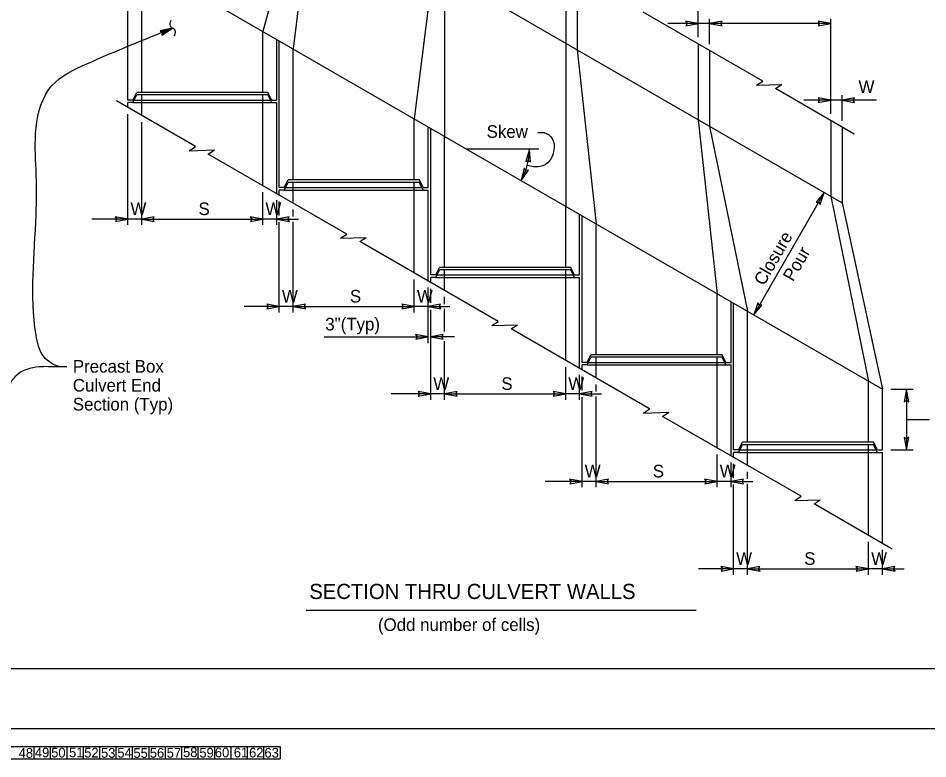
# Model space of a CAD drawing. Extents: x 0 to 2.83, y -0.03 to 1.83.
# Drawn here: x 0.902 to 1.84, y -0.031 to 0.733 of the extents above; entities that cross this region are included whole.
import ezdxf

# ---------------------------------------------------------------- set-up
doc = ezdxf.new("R2010")
doc.units = 0
for name, color, linetype in [('48', 7, 'Continuous'), ('49', 7, 'Continuous'), ('50', 7, 'Continuous'), ('51', 7, 'Continuous'), ('52', 7, 'Continuous'), ('53', 7, 'Continuous'), ('54', 7, 'Continuous'), ('55', 7, 'Continuous'), ('56', 7, 'Continuous'), ('57', 7, 'Continuous'), ('58', 7, 'Continuous'), ('59', 7, 'Continuous'), ('60', 7, 'Continuous'), ('61', 7, 'Continuous'), ('62', 7, 'Continuous'), ('63', 7, 'Continuous'), ('Default', 7, 'Continuous')]:
    doc.layers.add(name, color=color, linetype=linetype)

msp = doc.modelspace()

# ---------------------------------------------------------------- linework, layer by layer
at = {"layer": '50'}
for p, q in [((1.05641, 0.94429), (1.75172, 0.54286)), ((1.01474, 0.80001), (1.79339, 0.35046)), ((1.01995, 0.64881), (1.01474, 0.64881)), ((1.01995, 0.64881), (1.02386, 0.65662)), ((1.01995, 0.6462), (1.02386, 0.65402)), ((1.02125, 0.64881), (1.16188, 0.64881)), ((1.15927, 0.65662), (1.02386, 0.65662)), ((1.15927, 0.65402), (1.02386, 0.65402)), ((1.02906, 0.63277), (1.02906, 0.65402)), ((1.16318, 0.64881), (1.15927, 0.65662)), ((1.16318, 0.6462), (1.15927, 0.65402)), ((1.16318, 0.64881), (1.16839, 0.64881)), ((1.01474, 0.64104), (1.01474, 0.6462)), ((1.01995, 0.6462), (1.01474, 0.6462)), ((1.01995, 0.6462), (1.16318, 0.6462)), ((1.16318, 0.6462), (1.16839, 0.6462)), ((1.1762, 0.5586), (1.18011, 0.56641)), ((1.1762, 0.55599), (1.18011, 0.5638)), ((1.31552, 0.56641), (1.18011, 0.56641)), ((1.31552, 0.5638), (1.18011, 0.5638)), ((1.18531, 0.54256), (1.18531, 0.5638)), ((1.31943, 0.5586), (1.31552, 0.56641)), ((1.31943, 0.55599), (1.31552, 0.5638)), ((1.1762, 0.5586), (1.17099, 0.5586)), ((1.17099, 0.55083), (1.17099, 0.55599)), ((1.1762, 0.55599), (1.17099, 0.55599)), ((1.1762, 0.55599), (1.31943, 0.55599)), ((1.1775, 0.5586), (1.31813, 0.5586)), ((1.31943, 0.5586), (1.32464, 0.5586)), ((1.31943, 0.55599), (1.32464, 0.55599)), ((1.33245, 0.46839), (1.33636, 0.4762)), ((1.33245, 0.46578), (1.33636, 0.47359)), ((1.47177, 0.4762), (1.33636, 0.4762)), ((1.47177, 0.47359), (1.33636, 0.47359)), ((1.34156, 0.45235), (1.34156, 0.47359)), ((1.47568, 0.46839), (1.47177, 0.4762)), ((1.47568, 0.46578), (1.47177, 0.47359)), ((1.33245, 0.46839), (1.32724, 0.46839)), ((1.32724, 0.46062), (1.32724, 0.46578)), ((1.33245, 0.46578), (1.32724, 0.46578)), ((1.33245, 0.46578), (1.47568, 0.46578)), ((1.33375, 0.46839), (1.47438, 0.46839)), ((1.47568, 0.46839), (1.48089, 0.46839)), ((1.47568, 0.46578), (1.48089, 0.46578)), ((1.4887, 0.37817), (1.49261, 0.38599)), ((1.62802, 0.38599), (1.49261, 0.38599)), ((1.63193, 0.37817), (1.62802, 0.38599)), ((1.4887, 0.37817), (1.48349, 0.37817)), ((1.48349, 0.37041), (1.48349, 0.37557)), ((1.4887, 0.37557), (1.48349, 0.37557)), ((1.4887, 0.37557), (1.49261, 0.38338)), ((1.4887, 0.37557), (1.63193, 0.37557)), ((1.49, 0.37817), (1.63063, 0.37817)), ((1.62802, 0.38338), (1.49261, 0.38338)), ((1.49781, 0.36214), (1.49781, 0.38338)), ((1.63193, 0.37557), (1.62802, 0.38338)), ((1.63193, 0.37817), (1.63714, 0.37817)), ((1.63193, 0.37557), (1.63714, 0.37557)), ((1.64495, 0.28796), (1.64886, 0.29578)), ((1.64495, 0.28536), (1.64886, 0.29317)), ((1.78427, 0.29578), (1.64886, 0.29578)), ((1.78427, 0.29317), (1.64886, 0.29317)), ((1.65406, 0.27193), (1.65406, 0.29317)), ((1.78818, 0.28796), (1.78427, 0.29578)), ((1.78818, 0.28536), (1.78427, 0.29317)), ((1.64495, 0.28796), (1.63974, 0.28796)), ((1.63974, 0.2802), (1.63974, 0.28536)), ((1.64495, 0.28536), (1.63974, 0.28536)), ((1.64495, 0.28536), (1.78818, 0.28536)), ((1.64625, 0.28796), (1.78688, 0.28796)), ((1.78818, 0.28796), (1.79339, 0.28796)), ((1.78818, 0.28536), (1.79339, 0.28536))]:
    msp.add_line(p, q, dxfattribs=at)
at = {"layer": '54'}
for points in [[(1.60328, 0.72769), (1.59029, 0.73007), (1.5918, 0.72769), (1.59044, 0.72529)], [(1.615, 0.72769), (1.62799, 0.72532), (1.62649, 0.72769), (1.62784, 0.73009)], [(1.74, 0.72769), (1.72701, 0.73007), (1.72852, 0.72769), (1.72716, 0.72529)], [(1.74, 0.64876), (1.72701, 0.65113), (1.72852, 0.64876), (1.72716, 0.64636)], [(1.75172, 0.64876), (1.76471, 0.64638), (1.7632, 0.64876), (1.76456, 0.65116)], [(1.4291, 0.59799), (1.42553, 0.58527), (1.42804, 0.58656), (1.4303, 0.58498)], [(1.42047, 0.56577), (1.42818, 0.57649), (1.42538, 0.57615), (1.4238, 0.5784)], [(1.73341, 0.55343), (1.72486, 0.54336), (1.72767, 0.54348), (1.72907, 0.54111)], [(1.01474, 0.52603), (1.00175, 0.52841), (1.00326, 0.52603), (1.0019, 0.52363)], [(1.02906, 0.52603), (1.04206, 0.52366), (1.04055, 0.52603), (1.04191, 0.52843)], [(1.15406, 0.52603), (1.14107, 0.52841), (1.14258, 0.52603), (1.14122, 0.52363)], [(1.16839, 0.52603), (1.18138, 0.52366), (1.17987, 0.52603), (1.18123, 0.52843)], [(1.17099, 0.43582), (1.158, 0.4382), (1.15951, 0.43582), (1.15815, 0.43342)], [(1.18531, 0.43582), (1.19831, 0.43345), (1.1968, 0.43582), (1.19816, 0.43822)], [(1.31031, 0.43582), (1.29732, 0.4382), (1.29883, 0.43582), (1.29747, 0.43342)], [(1.32464, 0.43582), (1.33763, 0.43345), (1.33612, 0.43582), (1.33748, 0.43822)], [(1.66052, 0.42717), (1.66907, 0.43724), (1.66626, 0.43712), (1.66486, 0.4395)], [(1.32464, 0.40463), (1.31165, 0.407), (1.31315, 0.40463), (1.3118, 0.40223)], [(1.32724, 0.40463), (1.34023, 0.40225), (1.33873, 0.40463), (1.34008, 0.40703)], [(1.32724, 0.34561), (1.31425, 0.34798), (1.31576, 0.34561), (1.3144, 0.34321)], [(1.34156, 0.34561), (1.35456, 0.34323), (1.35305, 0.34561), (1.35441, 0.34801)], [(1.46656, 0.34561), (1.45357, 0.34798), (1.45508, 0.34561), (1.45372, 0.34321)], [(1.48089, 0.34561), (1.49388, 0.34323), (1.49237, 0.34561), (1.49373, 0.34801)], [(1.81815, 0.35046), (1.81578, 0.33747), (1.81815, 0.33898), (1.82055, 0.33762)], [(1.81815, 0.28796), (1.82053, 0.30096), (1.81815, 0.29945), (1.81575, 0.30081)], [(1.48349, 0.2554), (1.4705, 0.25777), (1.47201, 0.2554), (1.47065, 0.253)], [(1.49781, 0.2554), (1.51081, 0.25302), (1.5093, 0.2554), (1.51066, 0.2578)], [(1.62281, 0.2554), (1.60982, 0.25777), (1.61133, 0.2554), (1.60997, 0.253)], [(1.63714, 0.2554), (1.65013, 0.25302), (1.64862, 0.2554), (1.64998, 0.2578)], [(1.63974, 0.16519), (1.62675, 0.16756), (1.62826, 0.16519), (1.6269, 0.16279)], [(1.65406, 0.16519), (1.66706, 0.16281), (1.66555, 0.16519), (1.66691, 0.16759)], [(1.77906, 0.16519), (1.76607, 0.16756), (1.76758, 0.16519), (1.76622, 0.16279)], [(1.79339, 0.16519), (1.80638, 0.16281), (1.80487, 0.16519), (1.80623, 0.16759)]]:
    msp.add_lwpolyline(points, close=True, dxfattribs=at)
at = {"layer": '55'}
for p, q in [((1.60328, 0.71362), (1.60328, 0.81164)), ((1.66979, 0.66828), (1.54644, 0.7395)), ((1.615, 0.70629), (1.615, 0.7327)), ((1.74, 0.63469), (1.74, 0.7327)), ((1.60328, 0.72769), (1.57198, 0.72769)), ((1.615, 0.72769), (1.60328, 0.72769)), ((1.74, 0.72769), (1.615, 0.72769)), ((1.66332, 0.66401), (1.66979, 0.66828)), ((1.66332, 0.66401), (1.68963, 0.66484)), ((1.68316, 0.66056), (1.68963, 0.66484)), ((1.7643, 0.61372), (1.68316, 0.66056)), ((1.08441, 0.60082), (1.00291, 0.64787)), ((1.74, 0.64876), (1.7123, 0.64876)), ((1.75172, 0.64876), (1.74, 0.64876)), ((1.75172, 0.62735), (1.75172, 0.65377)), ((1.78725, 0.64876), (1.75172, 0.64876)), ((1.01474, 0.51995), (1.01474, 0.63437)), ((1.02906, 0.51995), (1.02906, 0.6261)), ((1.07793, 0.59655), (1.08441, 0.60082)), ((1.07793, 0.59655), (1.10425, 0.59738)), ((1.09778, 0.5931), (1.10425, 0.59738)), ((1.24066, 0.51061), (1.09778, 0.5931)), ((1.43874, 0.59799), (1.36466, 0.59799)), ((1.15406, 0.51995), (1.15406, 0.55393)), ((1.16839, 0.51995), (1.16839, 0.54566)), ((1.73341, 0.55343), (1.66052, 0.42717)), ((1.17099, 0.52966), (1.17099, 0.54416)), ((1.18531, 0.52854), (1.18531, 0.53589)), ((1.01474, 0.52603), (0.97769, 0.52603)), ((1.02906, 0.52603), (1.01474, 0.52603)), ((1.02906, 0.52603), (1.15406, 0.52603)), ((1.16839, 0.52603), (1.15406, 0.52603)), ((1.16839, 0.52603), (1.19087, 0.52603)), ((1.17099, 0.42974), (1.17099, 0.52273)), ((1.18531, 0.42974), (1.18531, 0.52324)), ((1.23418, 0.50634), (1.24066, 0.51061)), ((1.23418, 0.50634), (1.2605, 0.50717)), ((1.25403, 0.50289), (1.2605, 0.50717)), ((1.39691, 0.4204), (1.25403, 0.50289)), ((1.31031, 0.42974), (1.31031, 0.46372)), ((1.32464, 0.39787), (1.32464, 0.45545)), ((1.32724, 0.43944), (1.32724, 0.45395)), ((1.34156, 0.43813), (1.34156, 0.44568)), ((1.17099, 0.43582), (1.13481, 0.43582)), ((1.18531, 0.43582), (1.17099, 0.43582)), ((1.18531, 0.43582), (1.31031, 0.43582)), ((1.32464, 0.43582), (1.31031, 0.43582)), ((1.32464, 0.43582), (1.34699, 0.43582)), ((1.32724, 0.33953), (1.32724, 0.43252)), ((1.34156, 0.4099), (1.34156, 0.43328)), ((1.39043, 0.41613), (1.39691, 0.4204)), ((1.39043, 0.41613), (1.41675, 0.41696)), ((1.41028, 0.41268), (1.41675, 0.41696)), ((1.21717, 0.40463), (1.32464, 0.40463)), ((1.35188, 0.40463), (1.32724, 0.40463)), ((1.55316, 0.33019), (1.41028, 0.41268)), ((1.34156, 0.33953), (1.34156, 0.4002)), ((1.46656, 0.33953), (1.46656, 0.37351)), ((1.48089, 0.33953), (1.48089, 0.36524)), ((1.48349, 0.34923), (1.48349, 0.36374)), ((1.49781, 0.34811), (1.49781, 0.35547)), ((1.80196, 0.35046), (1.82499, 0.35046)), ((1.81815, 0.35046), (1.81815, 0.28796)), ((1.32724, 0.34561), (1.2866, 0.34561)), ((1.34156, 0.34561), (1.32724, 0.34561)), ((1.34156, 0.34561), (1.46656, 0.34561)), ((1.48089, 0.34561), (1.46656, 0.34561)), ((1.48089, 0.34561), (1.50337, 0.34561)), ((1.48349, 0.24932), (1.48349, 0.34231)), ((1.49781, 0.24932), (1.49781, 0.34307)), ((1.54668, 0.32592), (1.55316, 0.33019)), ((1.54668, 0.32592), (1.573, 0.32674)), ((1.56653, 0.32247), (1.573, 0.32674)), ((1.70941, 0.23998), (1.56653, 0.32247)), ((1.84192, 0.31878), (1.81815, 0.31878)), ((1.62281, 0.24932), (1.62281, 0.2833)), ((1.80196, 0.28796), (1.82499, 0.28796)), ((1.63714, 0.24932), (1.63714, 0.27503)), ((1.63974, 0.25902), (1.63974, 0.27353)), ((1.65406, 0.2579), (1.65406, 0.26526)), ((1.48349, 0.2554), (1.4455, 0.2554)), ((1.49781, 0.2554), (1.48349, 0.2554)), ((1.49781, 0.2554), (1.62281, 0.2554)), ((1.63714, 0.2554), (1.62281, 0.2554)), ((1.63714, 0.2554), (1.65962, 0.2554)), ((1.63974, 0.15911), (1.63974, 0.2521)), ((1.65406, 0.15911), (1.65406, 0.25285)), ((1.70293, 0.23571), (1.70941, 0.23998)), ((1.70293, 0.23571), (1.72925, 0.23653)), ((1.72278, 0.23226), (1.72925, 0.23653)), ((1.80354, 0.18563), (1.72278, 0.23226)), ((1.77906, 0.15911), (1.77906, 0.19309)), ((1.79339, 0.15911), (1.79339, 0.18482)), ((1.63974, 0.16519), (1.6035, 0.16519)), ((1.65406, 0.16519), (1.63974, 0.16519)), ((1.65406, 0.16519), (1.77906, 0.16519)), ((1.79339, 0.16519), (1.77906, 0.16519)), ((1.79339, 0.16519), (1.81587, 0.16519))]:
    msp.add_line(p, q, dxfattribs=at)
for points in [[(1.06097, 0.72311), (1.04813, 0.72025), (1.04993, 0.71898), (1.05819, 0.72192), (1.0503, 0.71804), (1.04997, 0.71587), (1.06095, 0.72309)], [(1.0563, 0.72174), (1.05035, 0.71952), (1.04943, 0.72009), (1.05963, 0.72254), (1.05075, 0.71693), (1.05099, 0.71802), (1.05652, 0.72058)]]:
    msp.add_lwpolyline(points, dxfattribs=at)
for centre, radius, start, end in [((1.06269, 0.72745), 0.0047, 131.78517, 248.19124), ((1.0592, 0.71873), 0.0047, 311.78517, 68.19124), ((1.36466, 0.59799), 0.06444, 330, 0)]:
    msp.add_arc(centre, radius, start, end, dxfattribs=at)
for points in [[(0.95184, 0.37351), (0.94669, 0.37351), (0.92779, 0.38445), (0.92005, 0.40634), (0.92005, 0.5301), (0.92005, 0.57678), (0.92005, 0.62022), (0.93638, 0.66366), (0.97246, 0.68624), (1.06095, 0.72309)], [(1.43792, 0.61522), (1.44415, 0.61522), (1.45245, 0.60929), (1.45349, 0.59328), (1.44578, 0.58231), (1.43318, 0.57993), (1.4269, 0.58131)], [(0.95184, 0.37351), (0.94161, 0.37351), (0.92297, 0.37345), (0.89978, 0.36478), (0.88869, 0.34904), (0.87866, 0.33797), (0.83439, 0.3372), (0.80458, 0.36301), (0.77828, 0.42143), (0.75487, 0.48444)]]:
    msp.add_spline(points, degree=3, dxfattribs=at)
at = {"layer": '62'}
for p, q in [((0.10494, -0.01804), (1.17174, -0.01804)), ((0.10496, -0.0181), (1.17175, -0.0181)), ((0.91774, -0.01804), (0.91774, -0.03074)), ((0.91775, -0.0181), (0.91775, -0.0308)), ((0.93468, -0.01804), (0.93468, -0.03074)), ((0.93469, -0.0181), (0.93469, -0.0308)), ((0.95161, -0.01804), (0.95161, -0.03074)), ((0.95162, -0.0181), (0.95162, -0.0308)), ((0.96854, -0.01804), (0.96854, -0.03074)), ((0.96855, -0.0181), (0.96855, -0.0308)), ((0.98548, -0.01804), (0.98548, -0.03074)), ((0.98549, -0.0181), (0.98549, -0.0308)), ((1.00241, -0.01804), (1.00241, -0.03074)), ((1.00242, -0.0181), (1.00242, -0.0308)), ((1.01934, -0.01804), (1.01934, -0.03074)), ((1.01935, -0.0181), (1.01935, -0.0308)), ((1.03628, -0.01804), (1.03628, -0.03074)), ((1.03629, -0.0181), (1.03629, -0.0308)), ((1.05321, -0.01804), (1.05321, -0.03074)), ((1.05322, -0.0181), (1.05322, -0.0308)), ((1.07014, -0.01804), (1.07014, -0.03074)), ((1.07015, -0.0181), (1.07015, -0.0308)), ((1.08708, -0.01804), (1.08708, -0.03074)), ((1.08709, -0.0181), (1.08709, -0.0308)), ((1.10401, -0.01804), (1.10401, -0.03074)), ((1.10402, -0.0181), (1.10402, -0.0308)), ((1.12094, -0.01804), (1.12094, -0.03074)), ((1.12095, -0.0181), (1.12095, -0.0308)), ((1.13788, -0.01804), (1.13788, -0.03074)), ((1.13789, -0.0181), (1.13789, -0.0308)), ((1.15481, -0.01804), (1.15481, -0.03074)), ((1.15482, -0.0181), (1.15482, -0.0308)), ((1.17174, -0.01804), (1.17174, -0.03074)), ((1.17175, -0.0181), (1.17175, -0.0308)), ((0.10494, -0.03074), (1.17174, -0.03074)), ((0.10496, -0.0308), (1.17175, -0.0308))]:
    msp.add_line(p, q, dxfattribs=at)
at = {"layer": '63'}
msp.add_line((2.83333, 0), (0, 0), dxfattribs=at)
at = {"layer": 'Default'}
for p, q in [((1.19313, 0.86536), (1.15406, 0.71958)), ((1.20485, 0.85859), (1.18531, 0.70153)), ((1.01474, 0.64881), (1.01474, 0.80001)), ((1.02906, 0.65662), (1.02906, 0.79175)), ((1.32985, 0.78643), (1.31031, 0.62937)), ((1.34156, 0.77966), (1.34156, 0.61132)), ((1.46656, 0.78562), (1.46656, 0.70749)), ((1.47828, 0.77885), (1.47828, 0.70072)), ((1.15406, 0.65662), (1.15406, 0.71958)), ((1.16839, 0.64881), (1.16839, 0.71131)), ((1.17099, 0.5586), (1.17099, 0.7098)), ((1.46656, 0.70749), (1.46656, 0.53915)), ((1.60328, 0.70668), (1.60328, 0.62856)), ((1.18531, 0.56641), (1.18531, 0.70153)), ((1.47828, 0.70072), (1.49781, 0.52111)), ((1.615, 0.69992), (1.615, 0.62179)), ((1.15406, 0.5606), (1.15406, 0.65402)), ((1.16839, 0.55233), (1.16839, 0.6462)), ((1.31031, 0.56641), (1.31031, 0.62937)), ((1.32464, 0.5586), (1.32464, 0.6211)), ((1.32724, 0.46839), (1.32724, 0.61959)), ((1.60328, 0.62856), (1.62281, 0.44894)), ((1.615, 0.62179), (1.65406, 0.4309)), ((1.74, 0.62775), (1.74, 0.54962)), ((1.75172, 0.62098), (1.75172, 0.54286)), ((1.34156, 0.4762), (1.34156, 0.61132)), ((1.31031, 0.47039), (1.31031, 0.5638)), ((1.32464, 0.46212), (1.32464, 0.55599)), ((1.74, 0.54962), (1.77906, 0.35873)), ((1.46656, 0.4762), (1.46656, 0.53915)), ((1.75172, 0.54286), (1.79339, 0.35046)), ((1.48089, 0.46839), (1.48089, 0.53089)), ((1.48349, 0.37817), (1.48349, 0.52938)), ((1.49781, 0.38599), (1.49781, 0.52111)), ((1.46656, 0.38018), (1.46656, 0.47359)), ((1.48089, 0.37191), (1.48089, 0.46578)), ((1.62281, 0.38599), (1.62281, 0.44894)), ((1.63714, 0.37817), (1.63714, 0.44067)), ((1.63974, 0.28796), (1.63974, 0.43917)), ((1.65406, 0.29578), (1.65406, 0.4309)), ((1.62281, 0.28997), (1.62281, 0.38338)), ((1.63714, 0.2817), (1.63714, 0.37557)), ((1.77906, 0.29578), (1.77906, 0.35873)), ((1.79339, 0.28796), (1.79339, 0.35046)), ((1.77906, 0.19976), (1.77906, 0.29317)), ((1.79339, 0.19149), (1.79339, 0.28536)), ((1.19871, 0.12254), (1.60103, 0.12254))]:
    msp.add_line(p, q, dxfattribs=at)
msp.add_lwpolyline([(2.72918, 1.77077), (0.10418, 1.77077), (0.10418, 0.06244), (2.72918, 0.06244)], close=True, dxfattribs=at)

# ---------------------------------------------------------------- texts
at = {"layer": '48'}
for p in [(0.90205, -0.02969), (0.90206, -0.02975)]:
    msp.add_text('48', height=0.01, dxfattribs=at).set_placement(p)
at = {"layer": '49'}
for p in [(0.91882, -0.02929), (0.91883, -0.02935)]:
    msp.add_text('49', height=0.01, dxfattribs=at).set_placement(p)
at = {"layer": '50'}
for p in [(0.93563, -0.02938), (0.93564, -0.02944)]:
    msp.add_text('50', height=0.01, dxfattribs=at).set_placement(p)
at = {"layer": '51'}
for p in [(0.95407, -0.02918), (0.95408, -0.02923)]:
    msp.add_text('51', height=0.01, dxfattribs=at).set_placement(p)
at = {"layer": '52'}
for p in [(0.96972, -0.02946), (0.96973, -0.02952)]:
    msp.add_text('52', height=0.01, dxfattribs=at).set_placement(p)
at = {"layer": '53'}
for p in [(0.98705, -0.0297), (0.98707, -0.02976)]:
    msp.add_text('53', height=0.01, dxfattribs=at).set_placement(p)
at = {"layer": '54'}
for p in [(1.0039, -0.02958), (1.00392, -0.02964)]:
    msp.add_text('54', height=0.01, dxfattribs=at).set_placement(p)
at = {"layer": '55'}
for p in [(1.02047, -0.02978), (1.02048, -0.02984)]:
    msp.add_text('55', height=0.01, dxfattribs=at).set_placement(p)
at = {"layer": '56'}
for p in [(1.03739, -0.02967), (1.03741, -0.02972)]:
    msp.add_text('56', height=0.01, dxfattribs=at).set_placement(p)
at = {"layer": '57'}
for s, height, p in [('W', 0.01302, (1.32991, 0.34972)), ('57', 0.01, (1.05482, -0.02955)), ('57', 0.01, (1.05483, -0.02961))]:
    msp.add_text(s, height=height, dxfattribs=at).set_placement(p)
at = {"layer": '58'}
for p in [(1.07167, -0.02898), (1.07168, -0.02903)]:
    msp.add_text('58', height=0.01, dxfattribs=at).set_placement(p)
at = {"layer": '59'}
for p in [(1.08852, -0.0295), (1.08853, -0.02955)]:
    msp.add_text('59', height=0.01, dxfattribs=at).set_placement(p)
at = {"layer": '60'}
for p in [(1.10448, -0.02929), (1.10449, -0.02935)]:
    msp.add_text('60', height=0.01, dxfattribs=at).set_placement(p)
at = {"layer": '61'}
for p in [(1.12406, -0.02929), (1.12407, -0.02935)]:
    msp.add_text('61', height=0.01, dxfattribs=at).set_placement(p)
at = {"layer": '62'}
for p in [(1.13984, -0.02938), (1.13986, -0.02943)]:
    msp.add_text('62', height=0.01, dxfattribs=at).set_placement(p)
at = {"layer": '63'}
for p in [(1.15568, -0.02958), (1.15569, -0.02963)]:
    msp.add_text('63', height=0.01, dxfattribs=at).set_placement(p)
at = {"layer": 'Default'}
for s, height, p in [('W', 0.01302, (1.76869, 0.65615)), ('Skew', 0.013021, (1.38496, 0.60982)), ('W', 0.01302, (1.01741, 0.53014)), ('S', 0.01302, (1.08763, 0.53014)), ('W', 0.01302, (1.15673, 0.53014)), ('W', 0.01302, (1.17366, 0.43993)), ('S', 0.01302, (1.24388, 0.43993)), ('W', 0.01302, (1.31298, 0.43993)), ('3"(Typ)', 0.013021, (1.21846, 0.41114)), ('Precast Box', 0.0130208, (0.95795, 0.36757)), ('Culvert End', 0.0130208, (0.95795, 0.34804)), ('S', 0.01302, (1.40013, 0.34972)), ('W', 0.01302, (1.46923, 0.34972)), ('Section (Typ)', 0.0130208, (0.95795, 0.32851)), ('W', 0.01302, (1.48616, 0.25951)), ('S', 0.01302, (1.55638, 0.25951)), ('W', 0.01302, (1.62548, 0.25951)), ('W', 0.01302, (1.64241, 0.1693)), ('S', 0.01302, (1.71263, 0.1693)), ('W', 0.01302, (1.78173, 0.1693)), ('SECTION THRU CULVERT WALLS', 0.015625, (1.20195, 0.13406)), ('(Odd number of cells)', 0.0130208, (1.27282, 0.1011))]:
    msp.add_text(s, height=height, dxfattribs=at).set_placement(p)
for s, p in [('Closure', (1.67119, 0.45643)), ('Pour', (1.70115, 0.46074))]:
    msp.add_text(s, height=0.013021, rotation=60, dxfattribs=at).set_placement(p)

doc.saveas('drawing.dxf')
